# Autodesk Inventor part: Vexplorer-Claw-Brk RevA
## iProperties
Created: 2007-10
Part Number: Vexplorer-Claw-Brk RevA
Document SubType Name: Modeling
Material: Aluminum-6061-AHC
Density: 2.71 g/cm^3
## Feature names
1. Base1
